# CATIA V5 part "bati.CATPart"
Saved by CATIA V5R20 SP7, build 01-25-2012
Part number: bati
Publications: "Plan.36", "Plan.2"
Bounding box of the stored display mesh (mm): x -26.69 to 42.31, y -84 to 59.777, z -42.962 to 82.962
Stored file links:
  F:\Travaux\Modélisations\CFAO_2011\CFAO_2011_MMS\CFAO_2011_MMS_DONE\CFAO_2011_MMS_jboiteux\Catia\bati.CATPart
  F:\Travaux\Modélisations\CFAO_2011\CFAO_2011_MMS\CFAO_2011_MMS_DONE\CFAO_2011_MMS_jboiteux\Catia\Part1.CATPart
  U:\finthinkmotion\stepper.CATProduct
  F:\Travaux\Modélisations\CFAO_2011\CFAO_2011_MMS\CFAO_2011_MMS_DONE\CFAO_2011_MMS_jboiteux\Catia\Part2.CATPart
  C:\Program Files (x86)\Dassault Systemes\B19\intel_a\reffiles\standard\MetricThinPitch.txt
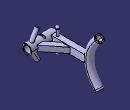
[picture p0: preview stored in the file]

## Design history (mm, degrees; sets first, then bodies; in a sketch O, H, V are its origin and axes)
Parameters
  royontubebati = 9 mm
Set1
  Plane1: linked copy from another document
  Point1: linked copy from another document
  DatumCurve1: linked copy from another document
  Line1: linked copy from another document
  Point2: linked copy from another document
  Point3: linked copy from another document
  Plane2: linked copy from another document
  Plane3: linked copy from another document
  Point4: linked copy from another document
  Plane4: linked copy from another document
  Plane5: linked copy from another document
  Line2: linked copy from another document
  Plane6: linked copy from another document
  Line3: linked copy from another document
  Point5: linked copy from another document
  Plane7: linked copy from another document
  Point6: linked copy from another document
  Plane8: linked copy from another document
  Point7: linked copy from another document
  Plane9: linked copy from another document
  Point8 to Point10: linked copy from another document
  Plane10: linked copy from another document
  Point11: linked copy from another document
  Plane11: linked copy from another document
  Plane12: linked copy from another document
Body1 (main body)
  Sketch1 on Plane1, origin (0, 0, 20), H (1, 0, 0), V (0, -1, 0)
    circle A1 centre (-17.69, -26.4) radius 9
    point P1 (-17.69, -26.4)
    reference projected point E1 (-17.69, -26.4) from Point1
    radius A1 = 9 {= royontubebati}
    coincidence: E1 P1
  Plane13: type 2Lines, Element1 DatumCurve1, Element2 Line1
  Sketch2 on Plane13, origin (-17.69, 0, 0), H (0, -1, 0), V (0, 0, 1)
    spline S1 through (-50.4, 74) (-26.4, 20) (-50.4, -34)
    reference projected point E1 (-50.4, -34) from Point3
    reference projected point E2 (-26.4, 20) from Point1
    reference projected point E3 (-50.4, 74) from Point2
    reference projected point E4 (-50.4, 74) from Point2
    point P1 (-50.4, 74)
    point P2 (-26.4, 20)
    point P3 (-50.4, -34)
    coincidence: E1 P3, E2 P2, E3 S1, E4 P1
  Rib1: profile Sketch1, centre curve Sketch2
  Sketch3 on Plane3, origin (-17.69, 0, 0), H (0, 1, 0), V (0, 0, 1)
    circle A1 centre (-72, 20) radius 12
    point P1 (-72, 20)
    reference projected point E1 (-72, 20) from Point4
    radius A1 = 12 {= royontubebati *4/3}
    coincidence: E1 P1
  Pad1: profile Sketch3, direction (1, 0, 0), up to Plane4, opposite side up to Plane5
  Sketch4 on face of Rib1, origin (0, 39.1283, -44.0193), H (-1, 0, 0), V (0, 0.7474, 0.6644)
    projected circle E1 centre (17.69, 15.0811) radius 9 from face of Rib1
  Pad2: profile Sketch4, direction (0, 0.6644, -0.7474), length 4
  Sketch5 on face of Rib1, origin (0, 58.9903, 66.3641), H (-1, 0, 0), V (0, -0.7474, 0.6644)
    projected circle E1 centre (17.69, 11.4935) radius 9 from edge [face of Rib1 | face of Rib1]
  Pad3: profile Sketch5, direction (0, 0.6644, 0.7474), length 4
  Shell1: ExtOffset 0, Face (end face of Pad2; end face of Pad3), IntOffset 2
  Sketch6 on Plane2, origin (0, 0, 0), H (-1, 0, 0), V (0, 0, 1)
    line L1 (10.49, 29) -> (24.89, 29)
    line L2 (24.89, 29) -> (24.89, 11)
    line L3 (24.89, 11) -> (10.49, 11)
    line L4 (10.49, 11) -> (10.49, 29)
    line L5 (12.49, 27) -> (22.89, 27)
    line L6 (22.89, 27) -> (22.89, 13)
    line L7 (22.89, 13) -> (12.49, 13)
    line L8 (12.49, 13) -> (12.49, 27)
    reference projected line E1 (-12.31, 20) -> (17.69, 20) from Line2
    reference projected line E2 (17.69, 65) -> (17.69, -25) from Line1
    reference projected line E3 (17.69, 65) -> (17.69, -25) from Line1
    length L4 = 18 {= royontubebati *2}
    distance E1 L3 = 9 {= royontubebati}
    distance L4 E2 = 7.2 {= 0.8*royontubebati}
    distance L2 E3 = 7.2 {= 0.8*royontubebati}
    distance L1 L5 = 2
    distance L7 L3 = 2
    distance L6 L2 = 2
    distance L8 L4 = 2
    horizontal: L1 H, L3 H, L5 H, L7 H
    vertical: L2 V, L4 V, L6 V, L8 V
  Pad4: profile Sketch6, direction (0, 1, 0), up to face of Pad1 from Sketch3.A1, opposite side up to face of Rib1
  Sketch7 on face of Pad4 from Sketch6.L3, origin (0, 0, 11), H (1, 0, 0), V (0, -1, 0)
    projected line E1 (18.31, 72) -> (-17.69, 27) from Line2
    projected line E2 (18.31, 72) -> (-10.49, 36) from Line2
    projected line E3 (-10.49, 64.0627) -> (-10.49, -21.6125) from edge [face of Pad4 from Sketch6.L3 | face of Pad4 from Sketch6.L4]
    point P5 (-10.49, 36)
    line L1 (-10.49, 36) -> (-10.49, 14.3895)
    line L2 (-10.49, 14.3895) -> (35.5984, 72)
    line L3 (35.5984, 72) -> (18.31, 72)
    distance L2 E1 = 13.5 {= royontubebati *1.5}
    coincidence: E3 P5
    vertical: L1 V
    horizontal: L3 H
  Pad5: profile Sketch7, direction (0, 0, 1), length 16 {= royontubebati *2-2mm}, opposite side length -2
  Sketch8 on Plane5, origin (42.31, 0, 0), H (0, 1, 0), V (0, 0, 1)
    circle A1 centre (-72, 20) radius 9.6
    point P1 (-72, 20)
    reference projected point E1 (-72, 20) from Point4
    radius A1 = 9.6 {= royontubebati *16/15}
    coincidence: E1 P1
  Sketch9 on Plane6, origin (0, 0, 20), H (1, 0, 0), V (0, -1, 0)
    construction line L1 (3.91, 66) -> (3.91, 78)
    point P1 (3.91, 66)
    line L2 (1.51, 66) -> (1.51, 78)
    line L3 (6.31, 78) -> (6.31, 66)
    arc A1 centre (3.91, 78) radius 2.4 from (1.51, 78) to (6.31, 78) cw
    arc A2 centre (3.91, 66) radius 2.4 from (6.31, 66) to (1.51, 66) cw
    reference projected line E1 (-17.69, 72) -> (32.31, 72) from Line3
    reference projected point E2 (3.91, 72) from Point9
    distance L1 L2 = 2.4 {= 8/30*royontubebati}
    distance P1 E1 = 6 {= royontubebati *2/3}
    length L2 = 12 {= royontubebati *4/3}
    distance E2 L1 = 0
    vertical: L1 V
    tangency: A1 L2, A2 L2, A1 L3, A2 L3
  Pocket1: profile Sketch9, direction (0, 0, 1), up to face of Pad1 from Sketch3.A1, opposite side up to face of Pad1 from Sketch3.A1
  Pocket2: profile Sketch8, direction (-1, 0, 0), up to face of Pad4 from Sketch6.L4
  Sketch10 on Plane4, origin (-26.69, 0, 0), H (0, 1, 0), V (0, 0, 1)
    circle A1 centre (-72, 20) radius 7.2
    point P1 (-72, 20)
    reference projected point E1 (-72, 20) from Point5
    radius A1 = 7.2 {= royontubebati *4/5}
    coincidence: E1 P1
  Pocket3: profile Sketch10, direction (-1, 0, 0), through (limit type 3)
  Sketch11 on Plane7, origin (0, 0, 20), H (1, 0, 0), V (0, -1, 0)
    circle A1 centre (-17.69, 54) radius 3
    point P1 (-17.69, 54)
    reference projected point E1 (-17.69, 54) from Point6
    radius A1 = 3 {= royontubebati *2/3/2}
    coincidence: E1 P1
  Pad6: profile Sketch11, direction (0, 0, -1), up to Plane11, opposite side up to face of Pad4 from Sketch6.L3
  Sketch12 on Plane7, origin (0, 0, 20), H (1, 0, 0), V (0, -1, 0)
    circle A1 centre (-17.69, 54) radius 3
    point P1 (-17.69, 54)
    reference projected point E1 (-17.69, 54) from Point6
    radius A1 = 3 {= royontubebati *2/3/2}
    coincidence: E1 P1
  Pad7: profile Sketch12, direction (0, 0, -1), up to face of Pad4 from Sketch6.L1, opposite side up to Plane12
  Sketch13 on Plane8, origin (-14.4328, 0, 24.9983), H (0, 1, 0), V (0.866, 0, 0.5)
    circle A1 centre (-72, 41.4454) radius 5
    point P1 (-72, 41.4454)
    reference projected point E1 (-72, 41.4454) from Point7
    radius A1 = 5 {= royontubebati *10/9/2}
    coincidence: E1 P1
  Pad8: profile Sketch13, direction (0.5, 0, -0.866), length -11.7 {= -royontubebati*1.3}, opposite side up to face of Pad1 from Sketch3.A1
  Sketch14 on Plane9, origin (2.8878, 0, 5.0017), H (0, 1, 0), V (-0.866, 0, 0.5)
    circle A1 centre (-72, -21.4454) radius 5
    point P1 (-72, -21.4454)
    reference projected point E1 (-72, -21.4454) from Point8
    radius A1 = 5 {= royontubebati *10/9/2}
    coincidence: E1 P1
  Pad9: profile Sketch14, direction (0.5, 0, 0.866), length -11.7 {= -royontubebati*1.3}, opposite side up to face of Pad1 from Sketch3.A1
  Plane14: type OffsetPt, RefPlane xy-plane, RefPoint Point10
  Sketch15 on Plane14, origin (0, 0, -7.6), H (1, 0, 0), V (0, 1, 0)
    arc A1 centre (-17.69, -54) radius 4 from (-17.69, -58) to (-17.69, -50) ccw
    point P1 (-17.69, -54)
    reference projected point E1 (-17.69, -54) from Point10
    line L1 (-17.69, -58) -> (-17.69, -50)
    reference projected point E2 (-17.69, -54) from Point10
    radius A1 = 4 {= royontubebati *2/2/3+1mm}
    coincidence: E1 P1, E2 L1
    vertical: L1 V
  Shaft1: profile Sketch15, axis Sketch15.L1, angle 360
  Plane15: type OffsetPt, RefPlane Plane10, RefPoint Point11
  Sketch16 on Plane15, origin (0, 0, 47.6), H (1, 0, 0), V (0, -1, 0)
    arc A1 centre (-17.69, 54) radius 4 from (-17.69, 50) to (-17.69, 58) ccw
    point P1 (-17.69, 54)
    reference projected point E1 (-17.69, 54) from Point11
    line L1 (-17.69, 50) -> (-17.69, 58)
    reference projected point E2 (-17.69, 54) from Point11
    radius A1 = 4 {= royontubebati *2/3/2+1mm}
    coincidence: E1 P1, E2 L1
    vertical: L1 V
  Shaft2: profile Sketch16, axis Sketch16.L1, angle 360
  Point12: stored without definition
  Plane16: type OffsetPt, RefPlane Plane7, RefPoint Point12
Relations
  Pad6.FirstLimit.Length = royontubebati *10/3 (deactivated)
  Pad7.SecondLimit.Length = royontubebati *10/3 (deactivated)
